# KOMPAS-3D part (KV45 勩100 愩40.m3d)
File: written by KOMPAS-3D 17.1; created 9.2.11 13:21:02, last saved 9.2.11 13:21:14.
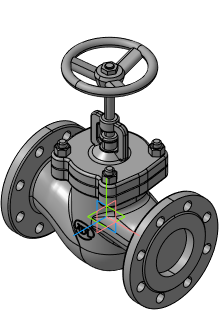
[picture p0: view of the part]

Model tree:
1. Плоскость XY
2. Плоскость ZX
3. Плоскость ZY
4. Ось X
5. Ось Y
6. Ось Z
7. Начало координат
8. Операция без истории:2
